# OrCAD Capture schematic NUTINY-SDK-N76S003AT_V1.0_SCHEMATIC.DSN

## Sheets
1 Nu-Link2-Me: size A3; title: Nu-Link2-Me; rev: 1.0; company: CMHuang; note: Nu-Link2-Me
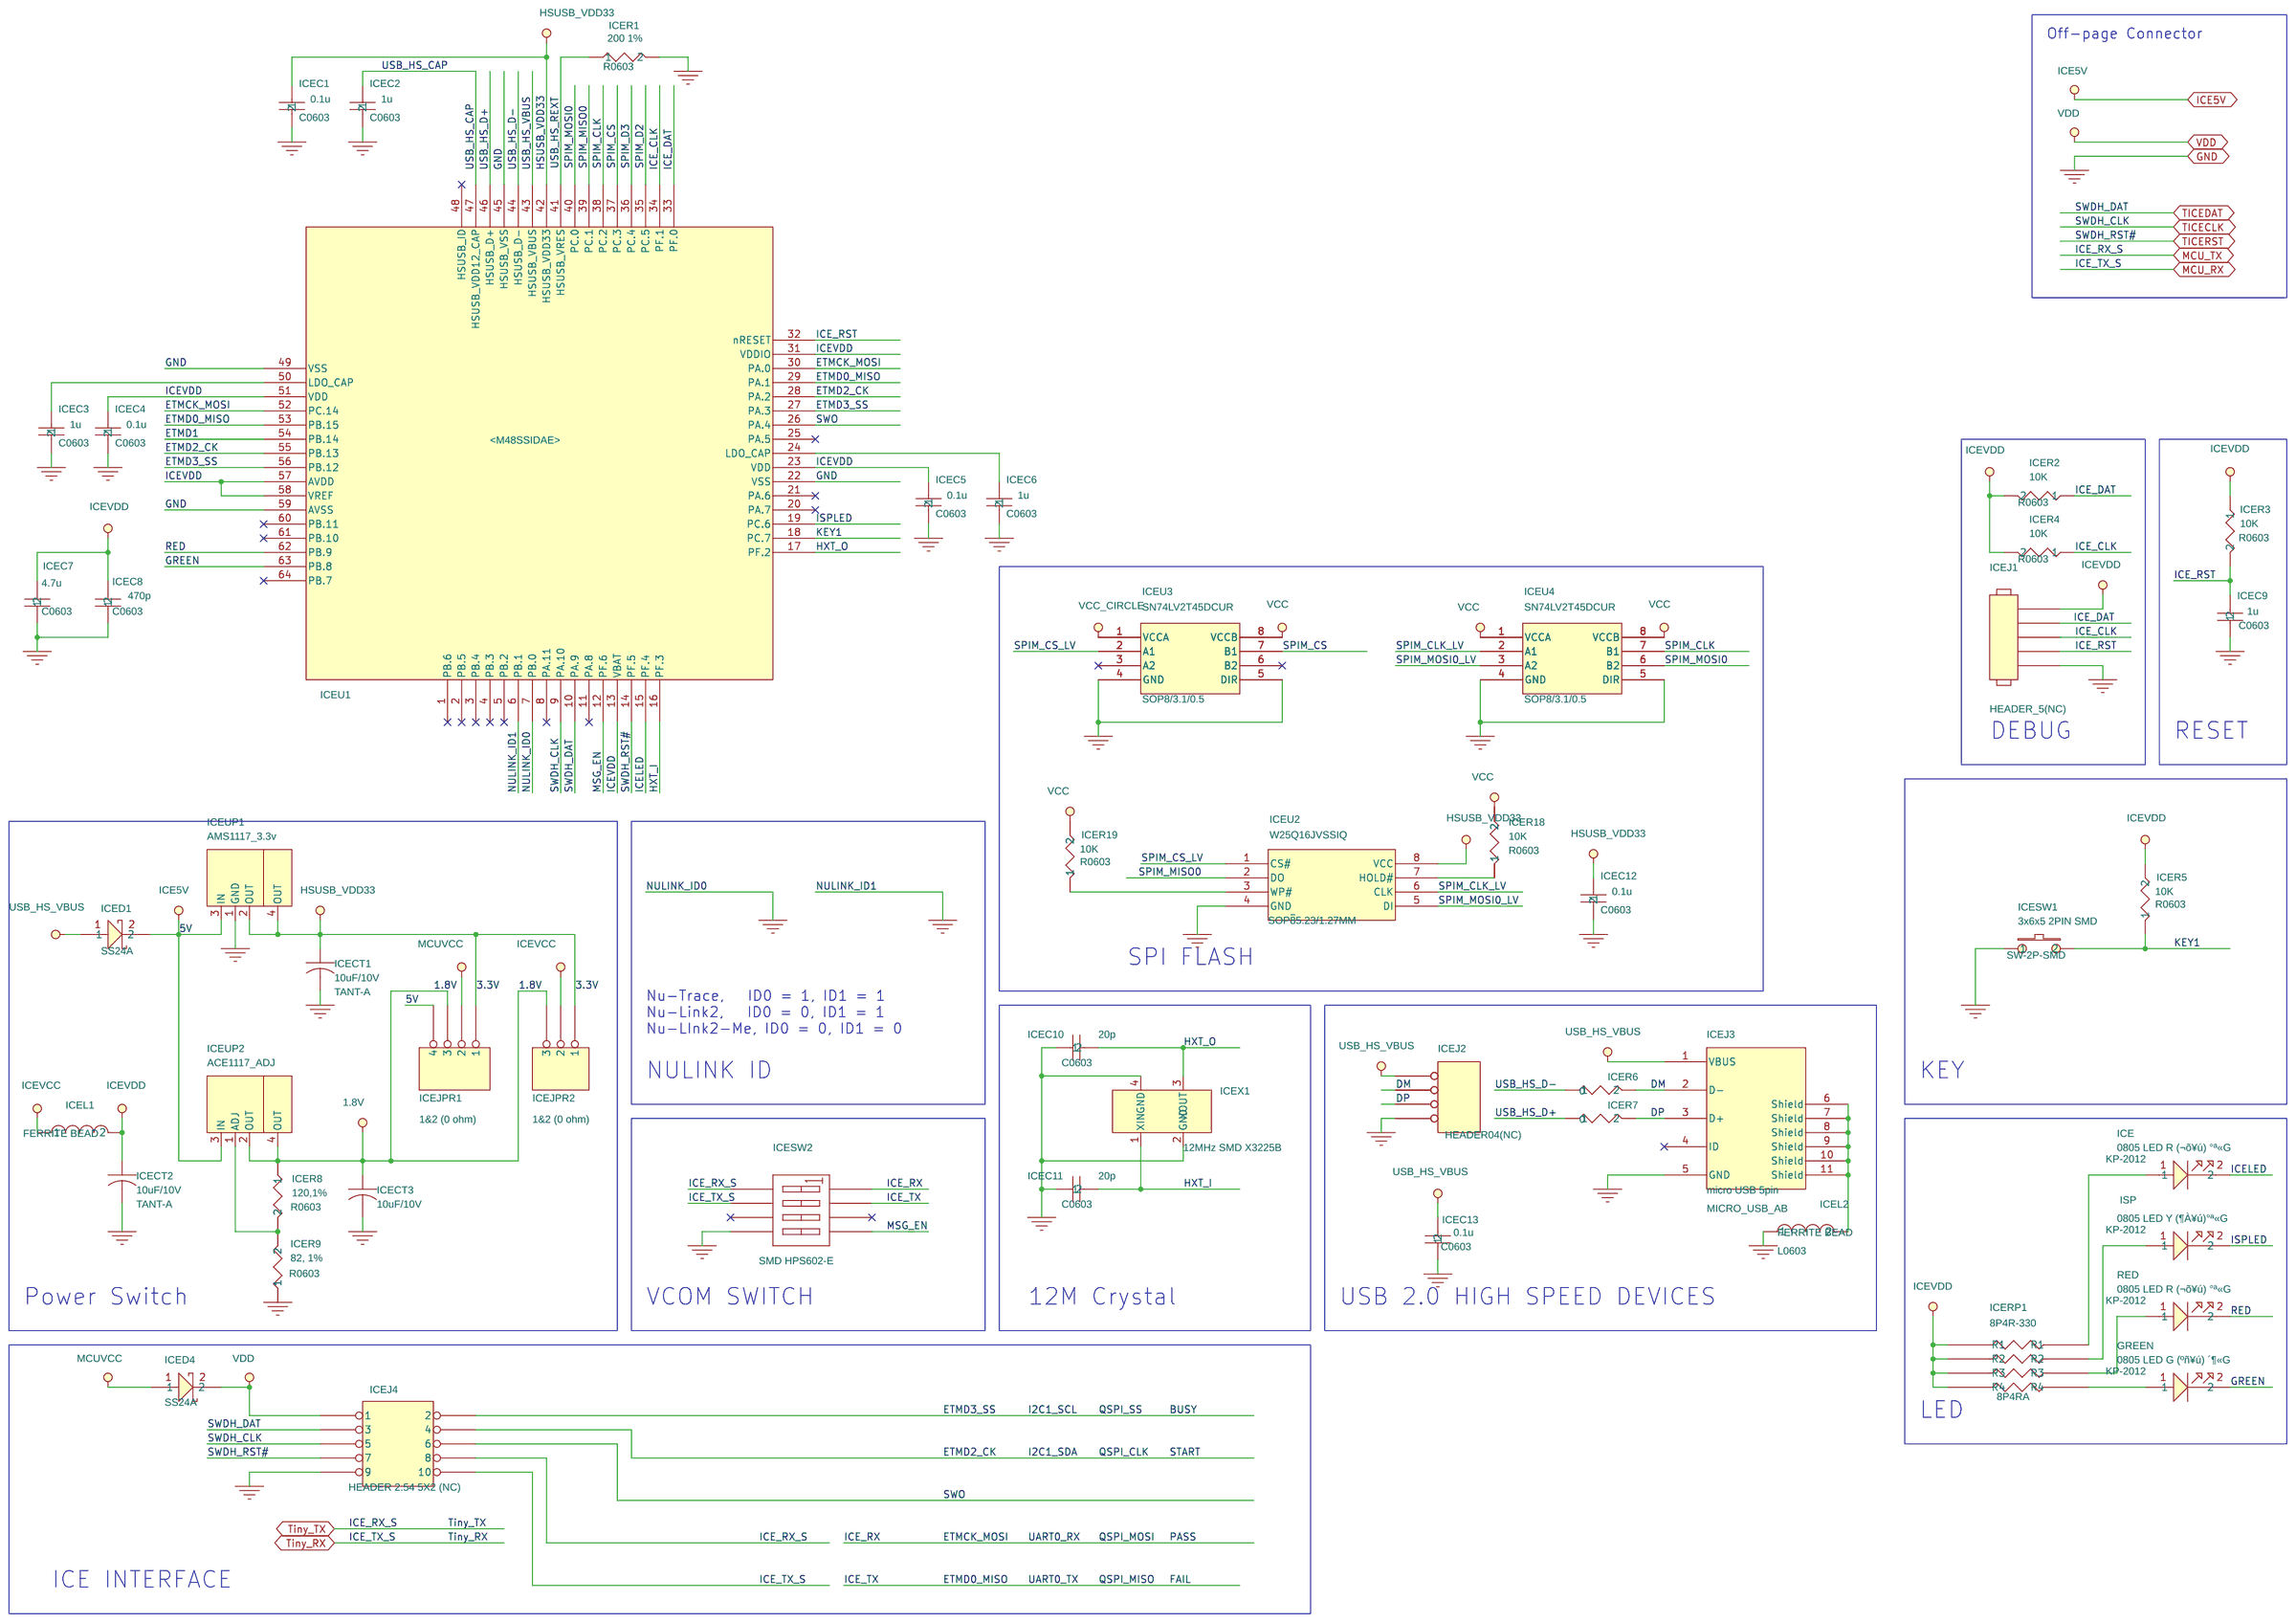
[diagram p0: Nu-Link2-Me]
2 NuTiny-N76S003AT20: size A4; title: SDK Circuit; note: 2
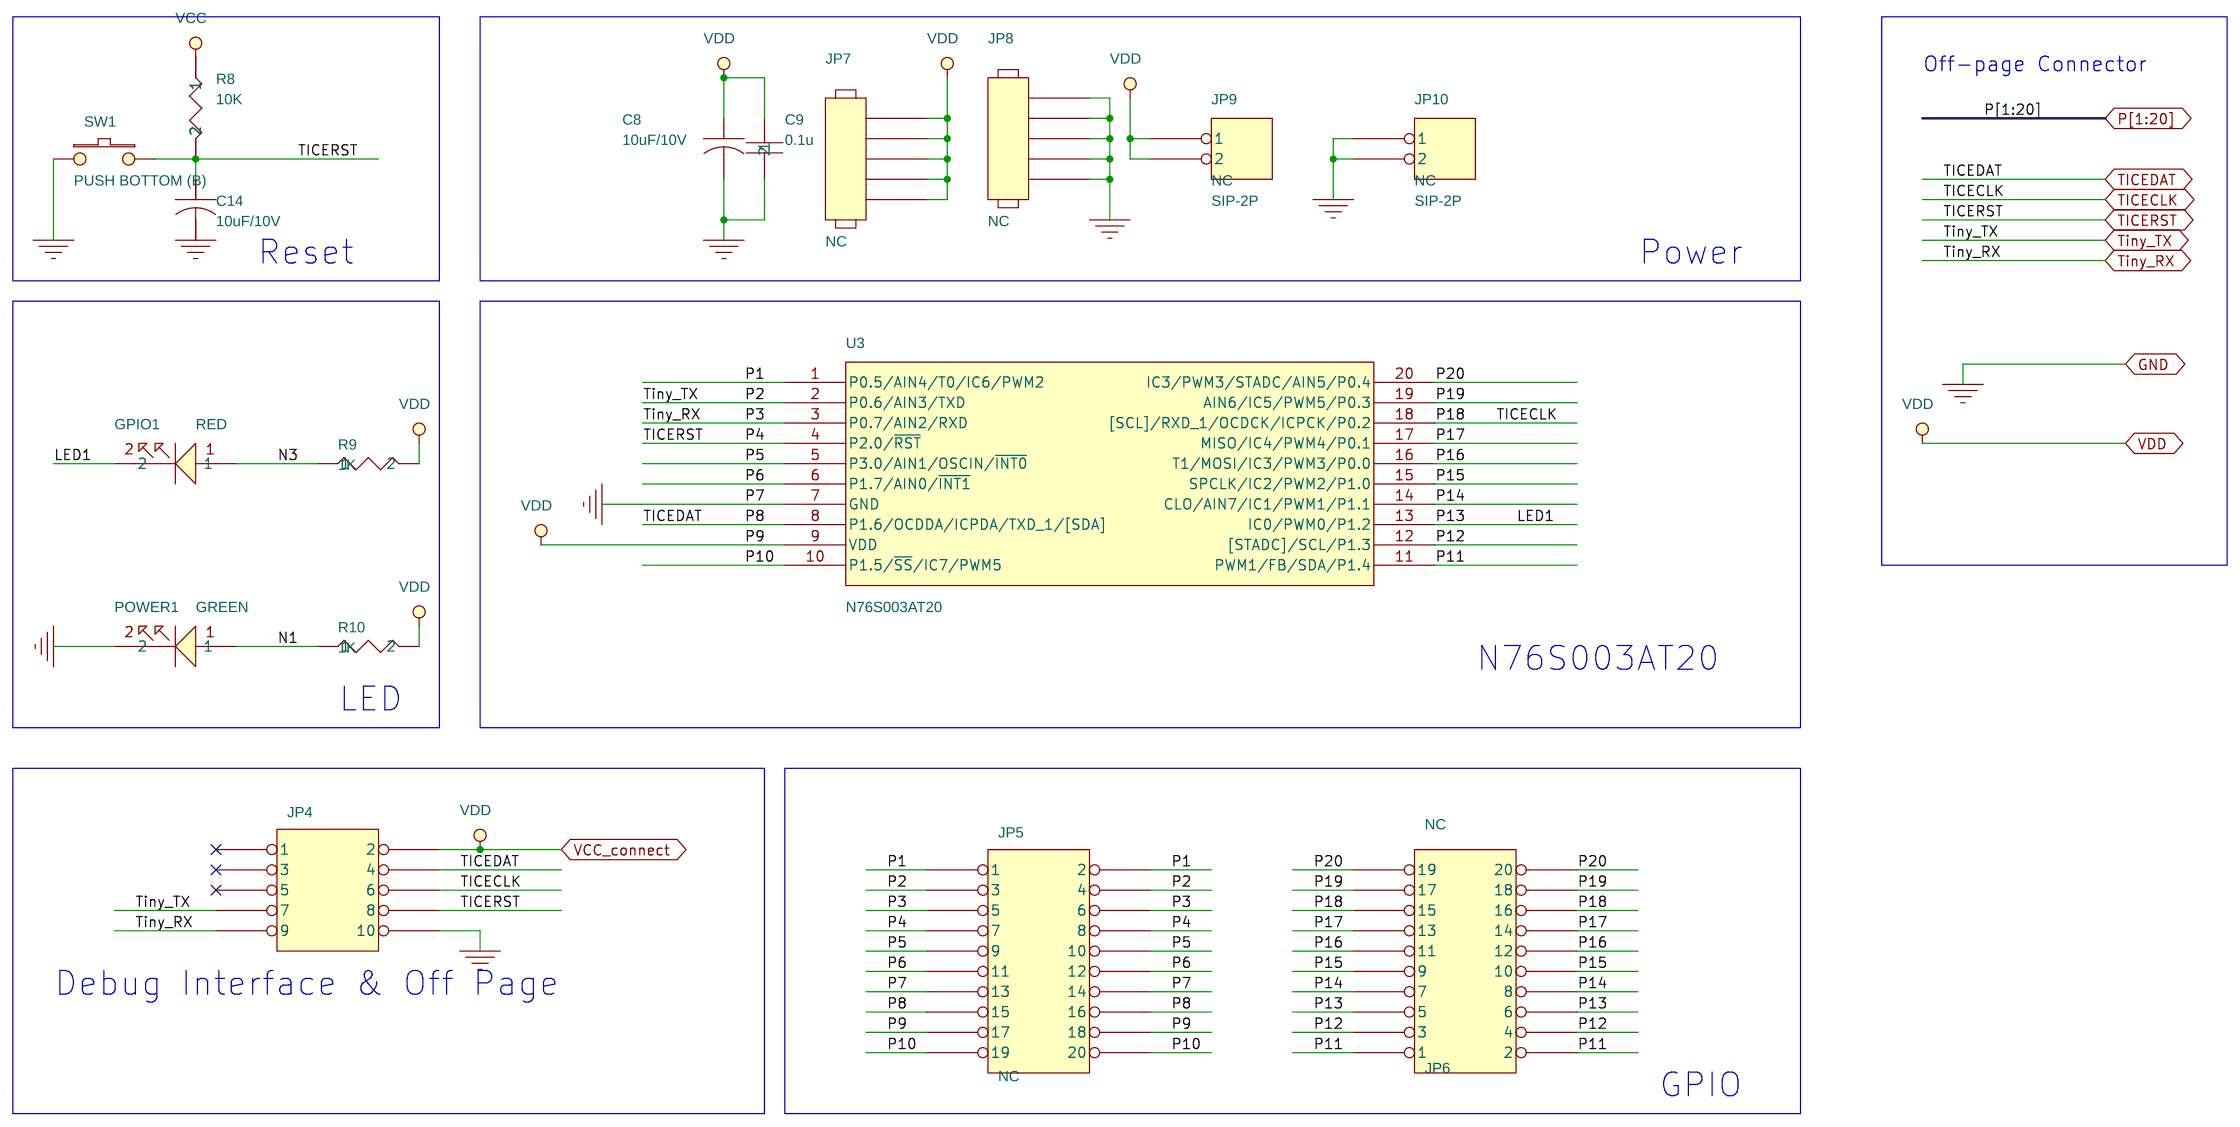
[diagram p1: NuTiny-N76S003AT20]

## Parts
sheet Nu-Link2-Me
GREEN  0805 LED G (ºñ¥ú) ´¶«G  [KP-2012]
ICE  0805 LED R (¬õ¥ú) °ª«G  [KP-2012]
ICEC1  0.1u  [C0603]
ICEC2  1u  [C0603]
ICEC3  1u  [C0603]
ICEC4  0.1u  [C0603]
ICEC5  0.1u  [C0603]
ICEC6  1u  [C0603]
ICEC7  4.7u  [C0603]
ICEC8  470p  [C0603]
ICEC9  1u  [C0603]
ICEC10  20p  [C0603]
ICEC11  20p  [C0603]
ICEC12  0.1u  [C0603]
ICEC13  0.1u  [C0603]
ICECT1  10uF/10V  [TANT-A]
ICECT2  10uF/10V  [TANT-A]
ICECT3  10uF/10V  [TANT-A]
ICED1  SS24A  [RB060L]
ICED4  SS24A  [RB060L]
ICEJ1  HEADER_5(NC)  [HEADER5X1]
ICEJ2  HEADER04(NC)  [HEADER04]
ICEJ3  micro USB 5pin  [MICRO_USB_AB]
ICEJ4  HEADER 2.54 5X2 (NC)  [HEADER5X2]
ICEJPR1  1&2 (0 ohm)  [R0603X3]
ICEJPR2  1&2 (0 ohm)  [R0603X2]
ICEL1  FERRITE BEAD  [L0603]
ICEL2  FERRITE BEAD  [L0603]
ICER1  200 1%  [R0603]
ICER2  10K  [R0603]
ICER3  10K  [R0603]
ICER4  10K  [R0603]
ICER5  10K  [R0603]
ICER6  0  [R0603]
ICER7  0  [R0603]
ICER8  120,1%  [R0603]
ICER9  82, 1%  [R0603]
ICER18  10K  [R0603]
ICER19  10K  [R0603]
ICERP1  8P4R-330  [8P4RA]
ICESW1  3x6x5 2PIN SMD  [SW-2P-SMD]
ICESW2  SMD HPS602-E  [SW1X4]
ICEU1  M48SSIDAE  [LQFP64_7x7_M48SSIDAE]
ICEU2  W25Q16JVSSIQ  [SOP8\5.23/1.27MM]
ICEU3  SN74LV2T45DCUR  [SOP8/3.1/0.5]
ICEU4  SN74LV2T45DCUR  [SOP8/3.1/0.5]
ICEUP1  AMS1117_3.3v  [SOT-223-1]
ICEUP2  ACE1117_ADJ  [SOT-223-1]
ICEX1  12MHz SMD X3225B  [CRYSTAL_SMD]
ISP  0805 LED Y (¶À¥ú)°ª«G  [KP-2012]
RED  0805 LED R (¬õ¥ú) °ª«G  [KP-2012]
sheet NuTiny-N76S003AT20
C8  10uF/10V  [TANT-A]
C9  0.1u  [C0603]
C14  10uF/10V  [TANT-A]
GPIO1  RED  [LED0805]
JP4  NC  [HEADER5X2]
JP5  NC  [header10x2]
JP6  NC  [header10x2]
JP7  NC  [SIP-5P]
JP8  NC  [SIP-5P]
JP9  NC  [SIP-2P]
JP10  NC  [SIP-2P]
POWER1  GREEN  [LED0805]
R8  10K  [R0603]
R9  1K  [R0603]
R10  1K  [R0603]
SW1  PUSH BOTTOM (B)  [SW-2P-SMD]
U3  N76S003AT20  [TSSOP20]

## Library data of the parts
GREEN = LED_0_2: Vendor: Kingbright
ICE = LED_0_3: Vendor: Kingbright
ICEC1 = CAP-C_9: Package: 0603; element_no: C0004
ICEC2 = CAP-C_10: Package: 0603; element_no: C0006
ICEC3 = CAP-C_12: Package: 0603; element_no: C0006
ICEC4 = CAP-C_2: Package: 0603; element_no: C0004
ICEC5 = CAP-C_6: Package: 0603; element_no: C0004
ICEC6 = CAP-C_5: Package: 0603; element_no: C0006
ICEC7 = CAP-C: Package: 0603
ICEC8 = CAP-C_8: Package: 0603
ICEC9 = CAP-C_7: Package: 0603; element_no: C0006
ICEC10 = CAP-C_4: Package: 0603
ICEC11 = CAP-C_11: Package: 0603
ICEC12 = CAP-C_3: Package: 0603; element_no: C0004
ICEC13 = CAP-C_1: Package: 0603; element_no: C0004
C8 C14 ICECT1-ICECT3 = C_10uF_10V
ICED1 = D_SS24A
ICED4 = D_SS24A_1
ICEJ1 JP7 JP8 = HEADER_5
ICEJ2 = HEADER_4_v2
ICEJ3 = micro_USB_5pin_0
ICEJ4 JP4 = HEADER_5X2
ICEJPR1 = HEADER_3_0
ICEJPR2 = HEADER_3
ICEL1 = FERRITE_BEAD
ICEL2 = FERRITE_BEAD_1
ICER1 = R_0_5: Package: 0603
ICER2 = R_0_3: Package: 0603
ICER3 = R_0_6: Package: 0603
ICER4 = R_0_7: Package: 0603
ICER5 = R_0_2: Package: 0603
ICER6 = R_33
ICER7 = R_33_1
ICER8 = R_0_4: Package: 0603
ICER9 = R_0_8: Package: 0603
ICER18 = R_0_1: Package: 0603
ICER19 = R_0: Package: 0603
ICERP1 = R-PACK8_0
ICESW1 = SW_PUSHBUTTON_0
ICESW2 = SW_DIP-4_SM
ICEU1 = M487SIDAE_0: M487SIDAE: <M48SSIDAE>
ICEU2 = W25P10_20_40_SOIC_0: Package: SOP8; Vendor: WINBOND
ICEU3 ICEU4 = SN74LV2T45
ICEUP1 = TO-247_Regulator_10
ICEUP2 = TO-247_Regulator_0
ICEX1 = Crystal_SMD_1
ISP = LED_0: Vendor: Kingbright
RED = LED_0_1: Vendor: Kingbright
C9 = C_0.1u
GPIO1 = LED_RED
JP5 = HEADER_10X2_1
JP6 = HEADER_10X2
JP9 = HEADER_2_1
JP10 = HEADER_2
POWER1 = LED_GREEN
R8 = R_10K
R9 = R_1K_1
R10 = R_1K
SW1 = PUSH_BOTTOM_(B)
U3 = SA8191_LQFP_48L_2

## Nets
1.8V: ICECT3.1 ICEJPR1.3 ICEJPR2.3 ICER8.1 ICEUP2.2(OUT) ICEUP2.4(OUT)
3.3V: ICEC1.1 ICEC12.1 ICECT1.1 ICEJPR1.1 ICEJPR2.1 ICER18.2 ICER19.2 ICEU1.42(HSUSB_VDD33) ICEU2.8(VCC) ICEU3.1(VCCA) ICEU4.1(VCCA) ICEUP1.2(OUT) ICEUP1.4(OUT)
GND: C8.2 C9.2 C14.2 ICEC1.2 ICEC2.2 ICEC3.2 ICEC4.2 ICEC5.2 ICEC6.2 ICEC7.1 ICEC8.1 ICEC9.1 ICEC10.1 ICEC11.1 ICEC12.2 ICEC13.1 ICECT1.2 ICECT2.2 ICECT3.2 ICEJ1.5 ICEJ2.4 ICEJ3.5(GND) ICEJ4.9 ICEL2.1 ICER1.2 ICER9.1 ICESW1.1 ICESW2.4(A4) ICEU1.6(PB.1) ICEU1.7(PB.0) ICEU1.22(VSS) ICEU1.45(HSUSB_VSS) ICEU1.49(VSS) ICEU1.59(AVSS) ICEU2.4(GND) ICEU3.4(GND) ICEU3.5(DIR) ICEU4.4(GND) ICEU4.5(DIR) ICEUP1.1(GND) ICEX1.2(GND) ICEX1.4(GND) JP4.10 JP5.13 JP5.14 JP8.1 JP8.2 JP8.3 JP8.4 JP8.5 JP10.1 JP10.2 POWER1.2 SW1.1 U3.7(GND)
VDD: C8.1 C9.1 ICED4.2 ICEJ4.1 JP4.2 JP5.17 JP5.18 JP7.1 JP7.2 JP7.3 JP7.4 JP7.5 JP9.1 JP9.2 R8.1 R9.2 R10.2 U3.9(VDD)
BUSY: ICEJ4.2 ICEU1.27(PA.3) ICEU1.56(PB.12)
DM: ICEJ2.2 ICEJ3.2(D-) ICER6.2
DP: ICEJ2.3 ICEJ3.3(D+) ICER7.2
ETMD1: ICEU1.54(PB.14)
ETMD2_CK: ICEJ4.4 ICEU1.28(PA.2) ICEU1.55(PB.13)
GREEN: GREEN.2 ICEU1.63(PB.8)
HXT_I: ICEC11.2 ICEU1.16(PF.3) ICEX1.1(XIN)
HXT_O: ICEC10.2 ICEU1.17(PF.2) ICEX1.3(XOUT)
ICE5V: ICED1.2 ICEJPR1.4 ICEUP1.3(IN) ICEUP2.3(IN)
ICE_CLK: ICEJ1.3 ICER4.1 ICEU1.34(PF.1)
ICE_DAT: ICEJ1.2 ICER2.1 ICEU1.33(PF.0)
ICE_RST: ICEC9.2 ICEJ1.4 ICER3.2 ICEU1.32(nRESET)
ICE_RX: ICESW2.8(B1) ICEU1.30(PA.0) ICEU1.52(PC.14)
ICE_TX: ICESW2.7(B2) ICEU1.29(PA.1) ICEU1.53(PB.15)
ICELED: ICE.2 ICEU1.15(PF.4)
ICEVCC: ICEJPR2.2 ICEL1.1
ICEVDD: ICEC4.1 ICEC5.1 ICEC7.2 ICEC8.2 ICECT2.1 ICEJ1.1 ICEL1.2 ICER2.2 ICER3.1 ICER4.2 ICER5.2 ICERP1.1(R1) ICERP1.3(R2) ICERP1.5(R3) ICERP1.7(R4) ICEU1.13(VBAT) ICEU1.23(VDD) ICEU1.31(VDDIO) ICEU1.51(VDD) ICEU1.57(AVDD) ICEU1.58(VREF) ICEU3.8(VCCB) ICEU4.8(VCCB)
ISPLED: ICEU1.19(PC.6) ISP.2
KEY1: ICER5.1 ICESW1.2 ICEU1.18(PC.7)
MCU_RX: ICEJ4.10 ICESW2.2(A2) JP4.9 JP5.5 JP5.6 U3.3(P0.7/AIN2/RXD)
MCU_TX: ICEJ4.8 ICESW2.1(A1) JP4.7 JP5.3 JP5.4 U3.2(P0.6/AIN3/TXD)
MCUVCC: ICED4.1 ICEJPR1.2
MSG_EN: ICESW2.5(B4) ICEU1.12(PF.6)
N1: POWER1.1 R10.1
N3: GPIO1.1 R9.1
P1: JP5.1 JP5.2 U3.1(P0.5/AIN4/T0/IC6/PWM2)
P4: C14.1 ICEJ4.7 ICEU1.14(PF.5) JP4.8 JP5.7 JP5.8 R8.2 SW1.2 U3.4(P2.0/~{RST})
P5: JP5.9 JP5.10 U3.5(P3.0/AIN1/OSCIN/~{INT0})
P6: JP5.11 JP5.12 U3.6(P1.7/AIN0/~{INT1})
P8: ICEJ4.3 ICEU1.10(PA.9) JP4.4 JP5.15 JP5.16 U3.8(P1.6/OCDDA/ICPDA/TXD_1/[SDA])
P10: JP5.19 JP5.20 U3.10(P1.5/~{SS}/IC7/PWM5)
P11: JP6.1 JP6.2 U3.11(PWM1/FB/SDA/P1.4)
P12: JP6.3 JP6.4 U3.12([STADC]/SCL/P1.3)
P13: GPIO1.2 JP6.5 JP6.6 U3.13(IC0/PWM0/P1.2)
P14: JP6.7 JP6.8 U3.14(CLO/AIN7/IC1/PWM1/P1.1)
P15: JP6.9 JP6.10 U3.15(SPCLK/IC2/PWM2/P1.0)
P16: JP6.11 JP6.12 U3.16(T1/MOSI/IC3/PWM3/P0.0)
P17: JP6.13 JP6.14 U3.17(MISO/IC4/PWM4/P0.1)
P18: ICEJ4.5 ICEU1.9(PA.10) JP4.6 JP6.15 JP6.16 U3.18([SCL]/RXD_1/OCDCK/ICPCK/P0.2)
P19: JP6.17 JP6.18 U3.19(AIN6/IC5/PWM5/P0.3)
P20: JP6.19 JP6.20 U3.20(IC3/PWM3/STADC/AIN5/P0.4)
RED: ICEU1.62(PB.9) RED.2
SPIM_CLK: ICEU1.38(PC.2) ICEU4.7(B1)
SPIM_CLK_LV: ICEU2.6(CLK) ICEU4.2(A1)
SPIM_CS: ICEU1.37(PC.3) ICEU3.7(B1)
SPIM_CS_LV: ICEU2.1(CS#) ICEU3.2(A1)
SPIM_D2: ICEU1.35(PC.5)
SPIM_D3: ICEU1.36(PC.4)
SPIM_MISO0: ICEU1.39(PC.1) ICEU2.2(DO)
SPIM_MOSI0: ICEU1.40(PC.0) ICEU4.6(B2)
SPIM_MOSI0_LV: ICEU2.5(DI) ICEU4.3(A2)
SWO: ICEJ4.6 ICEU1.26(PA.4)
USB_HS_CAP: ICEC2.1 ICEU1.47(HSUSB_VDD12_CAP)
USB_HS_D+: ICER7.1 ICEU1.46(HSUSB_D+)
USB_HS_D-: ICER6.1 ICEU1.44(HSUSB_D-)
USB_HS_REXT: ICER1.1 ICEU1.41(HSUSB_VRES)
USB_HS_VBUS: ICEC13.2 ICED1.1 ICEJ2.1 ICEJ3.1(VBUS) ICEU1.43(HSUSB_VBUS)
N16840819: ICEC6.1 ICEU1.24(LDO_CAP)
N16840960: ICEC3.1 ICEU1.50(LDO_CAP)
N17019924: ICER8.2 ICER9.2 ICEUP2.1(ADJ)
N17029977: GREEN.1 ICERP1.8(R4)
N17029979: ICERP1.6(R3) RED.1
N17030004: ICERP1.4(R2) ISP.1
N17030010: ICE.1 ICERP1.2(R1)
N17042369: ICEJ3.6(Shield) ICEJ3.7(Shield) ICEJ3.8(Shield) ICEJ3.9(Shield) ICEJ3.10(Shield) ICEJ3.11(Shield) ICEL2.2
N17173336: ICER18.1 ICEU2.7(HOLD#)
N17173580: ICER19.1 ICEU2.3(WP#)

Not connected (* = marked no-connect by the designer): ICEJ3 4(ID)*; ICESW2 3(A3)* 6(B3)*; ICEU1 1(PB.6)* 2(PB.5)* 3(PB.4)* 4(PB.3)* 5(PB.2)* 8(PA.11)* 11(PA.8)* 20(PA.7)* 21(PA.6)* 25(PA.5)* 48(HSUSB_ID)* 60(PB.11)* 61(PB.10)* 64(PB.7)*; ICEU3 3(A2)* 6(B2)*; JP4 1* 3* 5*

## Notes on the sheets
sheet 1
- Off-page Connector
- DEBUG
- RESET
- SPI FLASH
- Nu-Trace,   ID0 = 1, ID1 = 1
  Nu-Link2,   ID0 = 0, ID1 = 1
  Nu-LInk2-Me, ID0 = 0, ID1 = 0
- NULINK ID
- KEY
- Power Switch
- VCOM SWITCH
- 12M Crystal
- USB 2.0 HIGH SPEED DEVICES
- LED
- ICE INTERFACE
sheet 2
- Off-page Connector
- Reset
- Power
- N76S003AT20
- LED
- Debug Interface & Off Page
- GPIO
